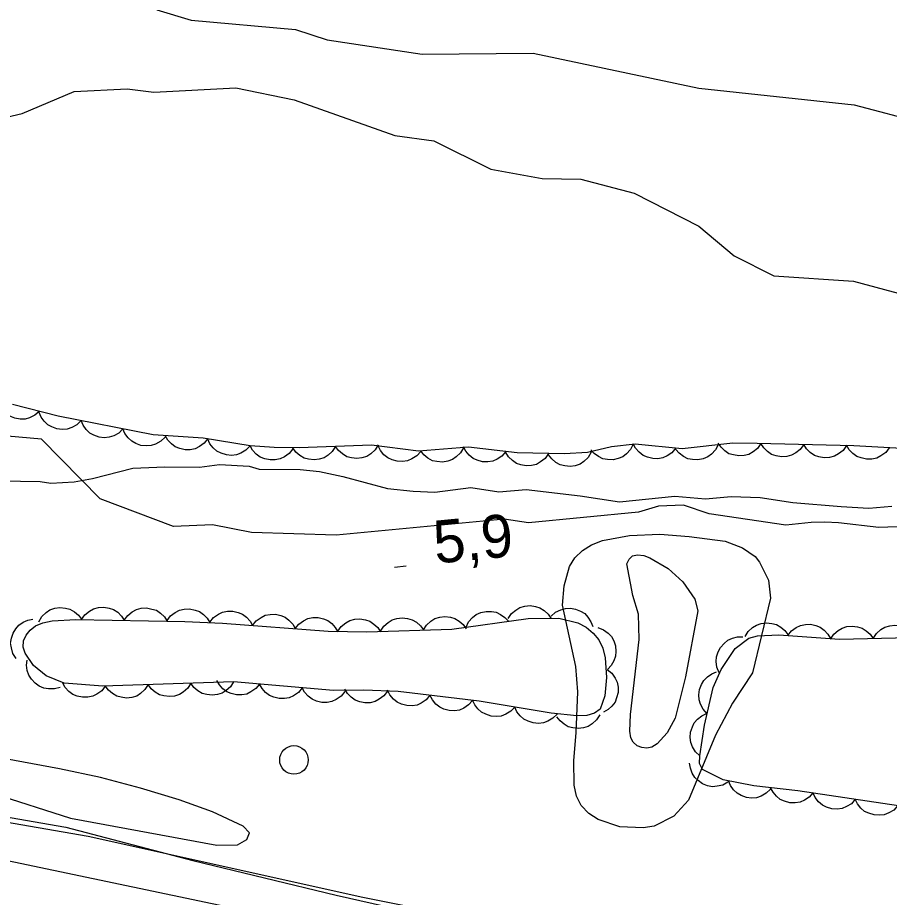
# Model space of a CAD drawing. Extents: x 336540 to 340074, y 5572036 to 5573747.
# Drawn here: x 336721.6 to 336782.8, y 5572625.9 to 5572687.6 of the extents above; entities that cross this region are included whole.
import ezdxf

# ---------------------------------------------------------------- set-up
doc = ezdxf.new("R2010")
doc.units = 0
for name, color, linetype in [('Niveau 1', 7, 'Continuous'), ('Niveau 2', 7, 'Continuous'), ('Niveau 21', 7, 'Continuous'), ('Niveau 22', 7, 'Continuous'), ('Niveau 3', 7, 'Continuous'), ('Niveau 36', 7, 'Continuous'), ('Niveau 44', 7, 'Continuous')]:
    doc.layers.add(name, color=color, linetype=linetype)

msp = doc.modelspace()

# ---------------------------------------------------------------- linework, layer by layer
at = {"layer": 'Niveau 1'}
for points in [[(336719.12, 5572680.18), (336721.97, 5572680.83), (336725.6, 5572682.39), (336729.32, 5572682.58), (336731.2, 5572682.33), (336736.94, 5572682.63), (336741.03, 5572681.81), (336748.1, 5572679.3), (336750.82, 5572678.93), (336754.82, 5572676.93), (336758.42, 5572676.29), (336761.13, 5572676.24), (336764.89, 5572675.25), (336769.42, 5572672.94), (336771.89, 5572670.86), (336774.67, 5572669.47), (336780.27, 5572669.08), (336787.14, 5572667.24)], [(336755.77, 5572652.39), (336743.97, 5572651.27), (336738.05, 5572651.47), (336735.31, 5572652.01), (336732.58, 5572651.88), (336727.42, 5572653.82), (336723.31, 5572658.01), (336720.93, 5572658.23)], [(336785.87, 5572651.96), (336782.04, 5572651.81), (336779.22, 5572652.14), (336778.26, 5572652.18), (336777.3, 5572652.16), (336775.51, 5572651.97), (336770.15, 5572652.78), (336768.34, 5572653.39), (336766.59, 5572653.31), (336765.18, 5572652.89), (336757.46, 5572652.15), (336755.77, 5572652.39)], [(336719.92, 5572633.16), (336725.34, 5572631.43), (336735.61, 5572629.55), (336737.06, 5572629.56), (336737.71, 5572629.95), (336737.9, 5572630.42), (336737.45, 5572630.87), (336735.3, 5572631.88), (336732.96, 5572632.72), (336730.25, 5572633.55), (336727.46, 5572634.28), (336724.57, 5572634.9), (336718.25, 5572636.06)]]:
    msp.add_lwpolyline(points, dxfattribs=at)
at = {"layer": 'Niveau 2'}
for points in [[(336731.4, 5572688.1), (336733.81, 5572687.39), (336741.12, 5572686.74), (336743.36, 5572686.01), (336750.01, 5572684.99), (336757.79, 5572685.08), (336769.42, 5572682.62), (336780.31, 5572681.46), (336785.11, 5572680.18)], [(336773.18, 5572641.63), (336771.78, 5572639.49), (336770.59, 5572637.26), (336768.7, 5572632.69), (336767.67, 5572631.57), (336766.28, 5572630.88), (336765.51, 5572630.75), (336763.88, 5572630.83), (336762.35, 5572631.34), (336761.69, 5572631.77), (336761.17, 5572632.33), (336760.84, 5572632.98), (336760.68, 5572633.75), (336760.64, 5572635.49), (336760.81, 5572637.41), (336760.93, 5572640.29), (336760.79, 5572642.06), (336759.85, 5572646.36), (336759.98, 5572647.73), (336760.35, 5572649.09), (336760.72, 5572649.7), (336761.25, 5572650.21), (336761.88, 5572650.61), (336762.66, 5572650.91), (336764.55, 5572651.26), (336766.67, 5572651.36), (336768.74, 5572651.19), (336771.26, 5572650.85), (336772.47, 5572650.4), (336773.36, 5572649.79), (336773.67, 5572649.39), (336774.29, 5572648.13), (336774.44, 5572646.87), (336773.18, 5572641.63)], [(336768.49, 5572641.34), (336767.76, 5572638.46), (336767.19, 5572637.41), (336766.5, 5572636.64), (336766.12, 5572636.42), (336765.76, 5572636.34), (336765.41, 5572636.39), (336765.09, 5572636.51), (336764.81, 5572636.76), (336764.65, 5572637.08), (336764.58, 5572637.54), (336764.62, 5572638.7), (336765.24, 5572643.96), (336765.19, 5572645.74), (336764.78, 5572647.04), (336764.37, 5572649.28), (336764.52, 5572649.6), (336764.76, 5572649.82), (336765.12, 5572649.89), (336765.55, 5572649.85), (336765.98, 5572649.7), (336767.27, 5572648.94), (336768.29, 5572648), (336769.14, 5572646.78), (336769.35, 5572645.97), (336768.49, 5572641.34)], [(336713.42, 5572632.82), (336725.03, 5572630.81), (336733.92, 5572628.47), (336743.97, 5572626.03), (336752.69, 5572624.08), (336763.24, 5572622.14), (336768.44, 5572621.3), (336771.02, 5572620.78), (336778.47, 5572618.92), (336781.06, 5572618.37), (336793.28, 5572616.04), (336801.03, 5572614.89), (336807.06, 5572613.73), (336818.29, 5572611.16), (336824.41, 5572609.93), (336829.29, 5572608.65), (336842, 5572605.62), (336849.91, 5572604.12), (336857.65, 5572602.37), (336860.36, 5572601.83), (336879.35, 5572598.2)]]:
    msp.add_lwpolyline(points, dxfattribs=at)
at = {"layer": 'Niveau 21'}
for points in [[(336606.59, 5572651.01), (336621.47, 5572648.81), (336627.74, 5572648.08), (336639.17, 5572646.47), (336647.1, 5572645.49), (336657.38, 5572643.66), (336675.17, 5572640.65), (336682.41, 5572638.89), (336706.84, 5572634.15), (336717.79, 5572631.7), (336726.58, 5572630.17), (336745.85, 5572625.9), (336758.27, 5572623.43), (336771.07, 5572620.58), (336780.38, 5572618.79), (336792.82, 5572616.01), (336801.98, 5572614.39), (336808.26, 5572613.12), (336817.36, 5572611.07), (336821.93, 5572609.72), (336824.69, 5572609.01), (336834.02, 5572607.19), (336854.11, 5572603.04), (336864.11, 5572601.24)], [(336884.31, 5572594.33), (336807.63, 5572610.39), (336785.16, 5572615.03), (336774.53, 5572617.32), (336763.55, 5572619.49), (336721.38, 5572628.36), (336711.63, 5572630.35), (336697.48, 5572632.86), (336693.75, 5572633.89), (336687.67, 5572635.19), (336673.64, 5572637.31), (336661.28, 5572639.55), (336653.39, 5572640.86), (336644.64, 5572642.06), (336630.46, 5572644.24), (336616.57, 5572646.25), (336606.76, 5572647.5)]]:
    msp.add_lwpolyline(points, dxfattribs=at)
at = {"layer": 'Niveau 22'}
msp.add_lwpolyline([(336720.47, 5572655.09), (336723.23, 5572655.03), (336723.97, 5572654.93), (336725.6, 5572655.02), (336726.9, 5572655.26), (336729.71, 5572655.98), (336731.97, 5572656.06), (336734.4, 5572656.04), (336735.8, 5572656.24), (336737.89, 5572656.12), (336738.58, 5572655.91), (336741.45, 5572655.88), (336742.8, 5572655.74), (336744.45, 5572655.38), (336747.57, 5572654.54), (336749.38, 5572654.36), (336750.9, 5572654.3), (336753.42, 5572654.61), (336755.39, 5572654.32), (336757.31, 5572654.49), (336761.1, 5572654.04), (336763.84, 5572653.61), (336767.73, 5572654.01), (336769.88, 5572653.83), (336771.68, 5572653.98), (336773.72, 5572653.91), (336776.01, 5572653.56), (336779.4, 5572653.3), (336781.33, 5572653.17), (336782.96, 5572653.32)], dxfattribs=at)
at = {"layer": 'Niveau 3'}
msp.add_line((336748.08, 5572649.04), (336748.88, 5572649.12), dxfattribs=at)
at = {"layer": 'Niveau 36'}
msp.add_circle((336741.019, 5572635.521), 1, dxfattribs=at)
at = {"layer": 'Niveau 44'}
for points in [[(336723.16, 5572659.96), (336722.85, 5572659.68), (336722.48, 5572659.51), (336722.16, 5572659.42), (336721.81, 5572659.41), (336721.45, 5572659.47), (336721.1, 5572659.63), (336720.81, 5572659.79), (336720.58, 5572660.05), (336720.37, 5572660.36), (336720.25, 5572660.7)], [(336783.65, 5572657.36), (336780.29, 5572657.55), (336773.51, 5572657.71), (336771.79, 5572657.73), (336768.25, 5572657.34), (336764.95, 5572657.67), (336763.3, 5572657.46), (336761.6, 5572657.07), (336759.99, 5572656.97), (336756.68, 5572657.05), (336753.26, 5572657.44), (336749.75, 5572657.17), (336746.46, 5572657.59), (336741.39, 5572657.41), (336739.63, 5572657.43), (336737.95, 5572657.54), (336734.66, 5572658.07), (336731.14, 5572658.32), (336724.48, 5572659.63), (336721.27, 5572660.44)], [(336726.09, 5572659.31), (336725.79, 5572659.02), (336725.43, 5572658.83), (336725.12, 5572658.71), (336724.77, 5572658.69), (336724.4, 5572658.73), (336724.05, 5572658.87), (336723.75, 5572659.01), (336723.5, 5572659.26), (336723.29, 5572659.56), (336723.14, 5572659.89)], [(336729.03, 5572658.73), (336728.74, 5572658.44), (336728.38, 5572658.25), (336728.07, 5572658.14), (336727.72, 5572658.11), (336727.35, 5572658.15), (336726.99, 5572658.29), (336726.7, 5572658.44), (336726.45, 5572658.68), (336726.23, 5572658.98), (336726.09, 5572659.31)], [(336731.98, 5572658.16), (336731.68, 5572657.86), (336731.32, 5572657.67), (336731.01, 5572657.56), (336730.66, 5572657.53), (336730.29, 5572657.57), (336729.93, 5572657.71), (336729.64, 5572657.86), (336729.39, 5572658.1), (336729.17, 5572658.4), (336729.03, 5572658.73)], [(336734.98, 5572658.05), (336734.72, 5572657.72), (336734.39, 5572657.49), (336734.1, 5572657.33), (336733.75, 5572657.27), (336733.38, 5572657.26), (336733.01, 5572657.35), (336732.7, 5572657.46), (336732.42, 5572657.68), (336732.17, 5572657.95), (336731.99, 5572658.26)], [(336737.94, 5572657.54), (336737.65, 5572657.24), (336737.3, 5572657.03), (336737, 5572656.91), (336736.65, 5572656.87), (336736.28, 5572656.9), (336735.91, 5572657.03), (336735.62, 5572657.16), (336735.36, 5572657.4), (336735.13, 5572657.69), (336734.98, 5572658.02)], [(336764.81, 5572657.65), (336764.63, 5572657.28), (336764.34, 5572656.99), (336764.09, 5572656.78), (336763.76, 5572656.65), (336763.4, 5572656.57), (336763.02, 5572656.59), (336762.69, 5572656.63), (336762.38, 5572656.79), (336762.08, 5572657), (336761.84, 5572657.27)], [(336767.8, 5572657.39), (336767.53, 5572657.06), (336767.19, 5572656.84), (336766.89, 5572656.7), (336766.55, 5572656.64), (336766.18, 5572656.65), (336765.81, 5572656.75), (336765.5, 5572656.87), (336765.23, 5572657.09), (336764.98, 5572657.37), (336764.81, 5572657.68)], [(336773.77, 5572657.71), (336773.54, 5572657.36), (336773.22, 5572657.11), (336772.93, 5572656.94), (336772.59, 5572656.86), (336772.22, 5572656.83), (336771.85, 5572656.9), (336771.53, 5572656.99), (336771.24, 5572657.19), (336770.97, 5572657.44), (336770.78, 5572657.74)], [(336776.77, 5572657.63), (336776.53, 5572657.29), (336776.21, 5572657.04), (336775.92, 5572656.88), (336775.58, 5572656.8), (336775.21, 5572656.77), (336774.84, 5572656.85), (336774.52, 5572656.94), (336774.24, 5572657.14), (336773.97, 5572657.4), (336773.77, 5572657.7)], [(336740.93, 5572657.34), (336740.68, 5572657.01), (336740.35, 5572656.78), (336740.05, 5572656.63), (336739.71, 5572656.56), (336739.34, 5572656.55), (336738.97, 5572656.64), (336738.66, 5572656.75), (336738.38, 5572656.96), (336738.12, 5572657.23), (336737.94, 5572657.54)], [(336743.94, 5572657.5), (336743.71, 5572657.15), (336743.41, 5572656.88), (336743.13, 5572656.7), (336742.79, 5572656.6), (336742.43, 5572656.55), (336742.05, 5572656.6), (336741.73, 5572656.68), (336741.43, 5572656.86), (336741.15, 5572657.1), (336740.94, 5572657.39)], [(336746.93, 5572657.61), (336746.71, 5572657.25), (336746.41, 5572656.99), (336746.13, 5572656.8), (336745.79, 5572656.7), (336745.43, 5572656.66), (336745.05, 5572656.71), (336744.73, 5572656.78), (336744.43, 5572656.97), (336744.15, 5572657.21), (336743.94, 5572657.5)], [(336749.91, 5572657.15), (336749.63, 5572656.84), (336749.28, 5572656.62), (336748.98, 5572656.49), (336748.63, 5572656.44), (336748.26, 5572656.46), (336747.9, 5572656.57), (336747.6, 5572656.69), (336747.33, 5572656.92), (336747.09, 5572657.21), (336746.93, 5572657.53)], [(336752.9, 5572657.41), (336752.69, 5572657.05), (336752.4, 5572656.77), (336752.13, 5572656.58), (336751.8, 5572656.46), (336751.43, 5572656.4), (336751.05, 5572656.44), (336750.73, 5572656.5), (336750.42, 5572656.67), (336750.13, 5572656.9), (336749.91, 5572657.18)], [(336755.88, 5572657.14), (336755.61, 5572656.82), (336755.26, 5572656.61), (336754.97, 5572656.47), (336754.62, 5572656.42), (336754.25, 5572656.43), (336753.88, 5572656.53), (336753.58, 5572656.65), (336753.31, 5572656.88), (336753.07, 5572657.16), (336752.9, 5572657.48)], [(336758.87, 5572657), (336758.63, 5572656.66), (336758.31, 5572656.41), (336758.02, 5572656.24), (336757.68, 5572656.16), (336757.31, 5572656.14), (336756.94, 5572656.21), (336756.62, 5572656.31), (336756.34, 5572656.51), (336756.07, 5572656.77), (336755.87, 5572657.07)], [(336761.87, 5572657.09), (336761.66, 5572656.73), (336761.36, 5572656.45), (336761.09, 5572656.26), (336760.75, 5572656.15), (336760.39, 5572656.1), (336760.01, 5572656.14), (336759.69, 5572656.21), (336759.38, 5572656.38), (336759.1, 5572656.62), (336758.88, 5572656.9)], [(336770.78, 5572657.62), (336770.59, 5572657.25), (336770.3, 5572656.96), (336770.04, 5572656.76), (336769.71, 5572656.63), (336769.35, 5572656.56), (336768.97, 5572656.58), (336768.64, 5572656.63), (336768.33, 5572656.8), (336768.03, 5572657.02), (336767.8, 5572657.29)], [(336779.77, 5572657.56), (336779.53, 5572657.22), (336779.21, 5572656.97), (336778.92, 5572656.81), (336778.58, 5572656.73), (336778.21, 5572656.7), (336777.84, 5572656.78), (336777.52, 5572656.87), (336777.23, 5572657.07), (336776.97, 5572657.33), (336776.77, 5572657.63)], [(336782.77, 5572657.41), (336782.52, 5572657.08), (336782.19, 5572656.84), (336781.89, 5572656.68), (336781.55, 5572656.61), (336781.18, 5572656.6), (336780.81, 5572656.69), (336780.5, 5572656.79), (336780.22, 5572657), (336779.96, 5572657.27), (336779.77, 5572657.58)], [(336723.13, 5572645.21), (336723.34, 5572645.57), (336723.64, 5572645.85), (336723.91, 5572646.04), (336724.25, 5572646.15), (336724.61, 5572646.2), (336724.99, 5572646.16), (336725.31, 5572646.09), (336725.62, 5572645.91), (336725.9, 5572645.68), (336726.12, 5572645.39)], [(336726.12, 5572645.36), (336726.36, 5572645.7), (336726.69, 5572645.95), (336726.97, 5572646.12), (336727.31, 5572646.21), (336727.68, 5572646.23), (336728.06, 5572646.16), (336728.37, 5572646.07), (336728.66, 5572645.87), (336728.93, 5572645.61), (336729.12, 5572645.31)], [(336729.12, 5572645.31), (336729.36, 5572645.65), (336729.68, 5572645.9), (336729.97, 5572646.07), (336730.31, 5572646.15), (336730.68, 5572646.18), (336731.06, 5572646.1), (336731.37, 5572646.01), (336731.66, 5572645.81), (336731.93, 5572645.55), (336732.12, 5572645.25)], [(336732.12, 5572645.29), (336732.37, 5572645.62), (336732.7, 5572645.86), (336732.99, 5572646.02), (336733.33, 5572646.1), (336733.7, 5572646.11), (336734.08, 5572646.03), (336734.39, 5572645.93), (336734.67, 5572645.72), (336734.93, 5572645.46), (336735.12, 5572645.15)], [(336735.12, 5572645.18), (336735.38, 5572645.5), (336735.72, 5572645.74), (336736.01, 5572645.89), (336736.36, 5572645.95), (336736.73, 5572645.95), (336737.1, 5572645.86), (336737.4, 5572645.75), (336737.68, 5572645.54), (336737.94, 5572645.26), (336738.11, 5572644.95)], [(336753.09, 5572644.83), (336753.27, 5572645.2), (336753.55, 5572645.5), (336753.8, 5572645.71), (336754.13, 5572645.85), (336754.49, 5572645.93), (336754.87, 5572645.92), (336755.19, 5572645.88), (336755.51, 5572645.72), (336755.82, 5572645.51), (336756.06, 5572645.25)], [(336756.04, 5572645.43), (336756.27, 5572645.78), (336756.59, 5572646.03), (336756.87, 5572646.21), (336757.21, 5572646.3), (336757.58, 5572646.34), (336757.95, 5572646.28), (336758.27, 5572646.19), (336758.56, 5572646), (336758.84, 5572645.75), (336759.04, 5572645.45)], [(336759.06, 5572645.59), (336759.37, 5572645.87), (336759.74, 5572646.05), (336760.06, 5572646.14), (336760.41, 5572646.15), (336760.77, 5572646.09), (336761.12, 5572645.94), (336761.41, 5572645.78), (336761.64, 5572645.52), (336761.85, 5572645.21), (336761.97, 5572644.87)], [(336721.54, 5572642.63), (336721.31, 5572642.98), (336721.2, 5572643.38), (336721.15, 5572643.7), (336721.2, 5572644.05), (336721.32, 5572644.4), (336721.52, 5572644.72), (336721.73, 5572644.98), (336722.02, 5572645.17), (336722.36, 5572645.33), (336722.71, 5572645.39)], [(336736.79, 5572641), (336727.62, 5572640.7), (336724.9, 5572640.9), (336723.65, 5572641.41), (336722.75, 5572642.15), (336722.16, 5572643), (336722.03, 5572643.43), (336722.06, 5572643.86), (336722.23, 5572644.26), (336722.52, 5572644.62), (336722.9, 5572644.92), (336723.4, 5572645.14), (336724.06, 5572645.27), (336725.72, 5572645.37), (336733.37, 5572645.23), (336736.01, 5572645.11), (336743.43, 5572644.55), (336746.13, 5572644.51), (336752.1, 5572644.69), (336757.44, 5572645.44), (336759.6, 5572645.46), (336760.92, 5572645.13), (336761.51, 5572644.82), (336762.01, 5572644.41), (336762.4, 5572643.93), (336762.68, 5572643.35), (336762.84, 5572642.68), (336762.94, 5572641.29), (336762.83, 5572640.01), (336762.5, 5572639.08), (336762.1, 5572638.79), (336761.56, 5572638.64), (336760.87, 5572638.61), (336759.05, 5572638.81), (336754.01, 5572639.64), (336748.32, 5572640.31), (336745.92, 5572640.42), (336743.8, 5572640.38), (336736.79, 5572641)], [(336738.11, 5572644.95), (336738.37, 5572645.28), (336738.71, 5572645.51), (336739, 5572645.66), (336739.35, 5572645.72), (336739.72, 5572645.73), (336740.09, 5572645.64), (336740.4, 5572645.53), (336740.67, 5572645.31), (336740.93, 5572645.04), (336741.11, 5572644.73)], [(336741.11, 5572644.73), (336741.37, 5572645.05), (336741.7, 5572645.28), (336741.99, 5572645.43), (336742.34, 5572645.5), (336742.71, 5572645.5), (336743.08, 5572645.41), (336743.39, 5572645.3), (336743.67, 5572645.08), (336743.92, 5572644.81), (336744.1, 5572644.5)], [(336744.1, 5572644.54), (336744.34, 5572644.88), (336744.66, 5572645.13), (336744.94, 5572645.3), (336745.28, 5572645.39), (336745.65, 5572645.41), (336746.03, 5572645.34), (336746.34, 5572645.25), (336746.63, 5572645.05), (336746.9, 5572644.8), (336747.1, 5572644.5)], [(336747.1, 5572644.54), (336747.32, 5572644.89), (336747.63, 5572645.16), (336747.91, 5572645.34), (336748.24, 5572645.44), (336748.61, 5572645.48), (336748.99, 5572645.43), (336749.31, 5572645.35), (336749.61, 5572645.17), (336749.89, 5572644.92), (336750.1, 5572644.63)], [(336750.1, 5572644.63), (336750.32, 5572644.98), (336750.63, 5572645.25), (336750.91, 5572645.43), (336751.24, 5572645.53), (336751.61, 5572645.57), (336751.99, 5572645.52), (336752.31, 5572645.44), (336752.61, 5572645.26), (336752.89, 5572645.01), (336753.1, 5572644.72)], [(336762.33, 5572644.8), (336762.72, 5572644.65), (336763.05, 5572644.41), (336763.28, 5572644.17), (336763.45, 5572643.86), (336763.56, 5572643.51), (336763.59, 5572643.13), (336763.58, 5572642.8), (336763.46, 5572642.47), (336763.27, 5572642.15), (336763.03, 5572641.88)], [(336772.66, 5572644.17), (336772.88, 5572644.53), (336773.18, 5572644.8), (336773.46, 5572644.98), (336773.79, 5572645.09), (336774.16, 5572645.14), (336774.54, 5572645.09), (336774.86, 5572645.02), (336775.16, 5572644.84), (336775.44, 5572644.6), (336775.66, 5572644.31)], [(336775.66, 5572644.24), (336775.91, 5572644.57), (336776.25, 5572644.8), (336776.54, 5572644.95), (336776.89, 5572645.02), (336777.25, 5572645.03), (336777.63, 5572644.94), (336777.93, 5572644.83), (336778.21, 5572644.61), (336778.47, 5572644.34), (336778.65, 5572644.03)], [(336778.65, 5572643.98), (336778.88, 5572644.33), (336779.19, 5572644.59), (336779.46, 5572644.77), (336779.8, 5572644.87), (336780.17, 5572644.91), (336780.55, 5572644.85), (336780.86, 5572644.77), (336781.16, 5572644.58), (336781.44, 5572644.34), (336781.65, 5572644.04)], [(336781.65, 5572644.04), (336781.87, 5572644.39), (336782.18, 5572644.66), (336782.46, 5572644.84), (336782.8, 5572644.93), (336783.17, 5572644.97), (336783.55, 5572644.92), (336783.86, 5572644.84), (336784.16, 5572644.65), (336784.44, 5572644.4), (336784.65, 5572644.11)], [(336814.83, 5572626.32), (336809.61, 5572627.54), (336801.55, 5572629.6), (336796.1, 5572630.77), (336784.52, 5572632.15), (336776.35, 5572633.36), (336773.28, 5572633.7), (336771.13, 5572634.13), (336769.67, 5572634.85), (336769.47, 5572635.26), (336769.48, 5572635.8), (336769.82, 5572637.96), (336770.42, 5572640.61), (336770.99, 5572641.86), (336771.96, 5572643.34), (336772.91, 5572644.06), (336773.53, 5572644.21), (336775.02, 5572644.28), (336779.27, 5572643.99), (336784.18, 5572644.1)], [(336770.84, 5572641.63), (336770.68, 5572642.02), (336770.64, 5572642.42), (336770.65, 5572642.75), (336770.76, 5572643.09), (336770.94, 5572643.41), (336771.2, 5572643.69), (336771.44, 5572643.91), (336771.77, 5572644.05), (336772.13, 5572644.14), (336772.49, 5572644.14)], [(336724.62, 5572640.61), (336724.22, 5572640.5), (336723.81, 5572640.5), (336723.48, 5572640.55), (336723.16, 5572640.69), (336722.86, 5572640.9), (336722.61, 5572641.19), (336722.42, 5572641.46), (336722.32, 5572641.79), (336722.27, 5572642.16), (336722.3, 5572642.52)], [(336762.99, 5572641.86), (336763.31, 5572641.6), (336763.54, 5572641.26), (336763.69, 5572640.97), (336763.75, 5572640.62), (336763.75, 5572640.25), (336763.65, 5572639.88), (336763.54, 5572639.58), (336763.32, 5572639.3), (336763.05, 5572639.05), (336762.73, 5572638.87)], [(336770, 5572638.76), (336769.72, 5572639.07), (336769.54, 5572639.43), (336769.43, 5572639.74), (336769.42, 5572640.09), (336769.47, 5572640.46), (336769.61, 5572640.81), (336769.77, 5572641.1), (336770.02, 5572641.35), (336770.33, 5572641.56), (336770.66, 5572641.69)], [(336736.79, 5572641), (336736.57, 5572640.65), (336736.26, 5572640.38), (336735.98, 5572640.2), (336735.65, 5572640.1), (336735.28, 5572640.05), (336734.9, 5572640.11), (336734.58, 5572640.18), (336734.28, 5572640.37), (336734, 5572640.61), (336733.79, 5572640.9)], [(336738.6, 5572640.84), (336738.34, 5572640.52), (336738, 5572640.29), (336737.71, 5572640.14), (336737.36, 5572640.08), (336736.99, 5572640.08), (336736.62, 5572640.18), (336736.31, 5572640.3), (336736.04, 5572640.51), (336735.79, 5572640.79), (336735.61, 5572641.1)], [(336727.79, 5572640.69), (336727.54, 5572640.36), (336727.2, 5572640.13), (336726.91, 5572639.98), (336726.56, 5572639.91), (336726.19, 5572639.91), (336725.82, 5572640), (336725.51, 5572640.11), (336725.23, 5572640.32), (336724.98, 5572640.6), (336724.8, 5572640.91)], [(336730.79, 5572640.8), (336730.57, 5572640.45), (336730.26, 5572640.18), (336729.99, 5572640), (336729.65, 5572639.9), (336729.28, 5572639.86), (336728.9, 5572639.91), (336728.59, 5572639.99), (336728.29, 5572640.17), (336728.01, 5572640.41), (336727.79, 5572640.71)], [(336733.79, 5572640.9), (336733.57, 5572640.55), (336733.26, 5572640.28), (336732.99, 5572640.1), (336732.65, 5572640), (336732.28, 5572639.96), (336731.9, 5572640.01), (336731.59, 5572640.09), (336731.28, 5572640.27), (336731, 5572640.51), (336730.79, 5572640.8)], [(336741.59, 5572640.58), (336741.33, 5572640.25), (336740.99, 5572640.02), (336740.69, 5572639.88), (336740.35, 5572639.82), (336739.98, 5572639.82), (336739.61, 5572639.92), (336739.3, 5572640.03), (336739.03, 5572640.25), (336738.78, 5572640.53), (336738.6, 5572640.84)], [(336744.58, 5572640.31), (336744.32, 5572639.99), (336743.98, 5572639.76), (336743.68, 5572639.61), (336743.34, 5572639.55), (336742.97, 5572639.55), (336742.6, 5572639.65), (336742.29, 5572639.77), (336742.01, 5572639.99), (336741.77, 5572640.26), (336741.59, 5572640.58)], [(336747.58, 5572640.34), (336747.33, 5572640.01), (336747, 5572639.77), (336746.71, 5572639.61), (336746.37, 5572639.53), (336746, 5572639.52), (336745.63, 5572639.6), (336745.32, 5572639.7), (336745.03, 5572639.91), (336744.77, 5572640.17), (336744.58, 5572640.48)], [(336750.56, 5572640.05), (336750.29, 5572639.73), (336749.95, 5572639.51), (336749.65, 5572639.37), (336749.3, 5572639.32), (336748.93, 5572639.34), (336748.56, 5572639.44), (336748.26, 5572639.57), (336747.99, 5572639.79), (336747.75, 5572640.08), (336747.58, 5572640.4)], [(336753.54, 5572639.69), (336753.27, 5572639.38), (336752.93, 5572639.16), (336752.63, 5572639.02), (336752.28, 5572638.97), (336751.91, 5572638.99), (336751.54, 5572639.09), (336751.24, 5572639.22), (336750.97, 5572639.44), (336750.73, 5572639.73), (336750.56, 5572640.05)], [(336756.51, 5572639.23), (336756.22, 5572638.93), (336755.87, 5572638.72), (336755.56, 5572638.6), (336755.21, 5572638.57), (336754.84, 5572638.6), (336754.48, 5572638.72), (336754.18, 5572638.86), (336753.92, 5572639.1), (336753.7, 5572639.39), (336753.55, 5572639.72)], [(336759.47, 5572638.74), (336759.18, 5572638.44), (336758.83, 5572638.24), (336758.52, 5572638.11), (336758.17, 5572638.08), (336757.8, 5572638.11), (336757.44, 5572638.23), (336757.14, 5572638.37), (336756.88, 5572638.61), (336756.66, 5572638.9), (336756.51, 5572639.23)], [(336762.46, 5572638.68), (336762.24, 5572638.32), (336761.94, 5572638.05), (336761.66, 5572637.87), (336761.33, 5572637.77), (336760.96, 5572637.72), (336760.58, 5572637.76), (336760.26, 5572637.84), (336759.96, 5572638.02), (336759.68, 5572638.26), (336759.46, 5572638.55)], [(336769.48, 5572635.81), (336769.18, 5572636.09), (336768.97, 5572636.44), (336768.85, 5572636.75), (336768.81, 5572637.1), (336768.84, 5572637.47), (336768.96, 5572637.83), (336769.09, 5572638.13), (336769.33, 5572638.39), (336769.62, 5572638.62), (336769.95, 5572638.77)], [(336771.46, 5572633.97), (336771.1, 5572633.76), (336770.7, 5572633.67), (336770.37, 5572633.64), (336770.03, 5572633.71), (336769.68, 5572633.84), (336769.37, 5572634.07), (336769.13, 5572634.29), (336768.95, 5572634.59), (336768.82, 5572634.94), (336768.77, 5572635.29)], [(336774.43, 5572633.47), (336774.14, 5572633.18), (336773.78, 5572632.99), (336773.47, 5572632.87), (336773.11, 5572632.85), (336772.75, 5572632.89), (336772.39, 5572633.03), (336772.1, 5572633.18), (336771.85, 5572633.43), (336771.63, 5572633.73), (336771.49, 5572634.06)], [(336777.43, 5572633.24), (336777.16, 5572632.92), (336776.82, 5572632.7), (336776.52, 5572632.56), (336776.17, 5572632.51), (336775.8, 5572632.52), (336775.43, 5572632.62), (336775.13, 5572632.75), (336774.86, 5572632.97), (336774.62, 5572633.25), (336774.45, 5572633.57)], [(336780.39, 5572632.76), (336780.11, 5572632.45), (336779.76, 5572632.25), (336779.46, 5572632.12), (336779.11, 5572632.08), (336778.74, 5572632.1), (336778.37, 5572632.22), (336778.08, 5572632.35), (336777.81, 5572632.59), (336777.58, 5572632.88), (336777.43, 5572633.2)], [(336783.36, 5572632.32), (336783.08, 5572632.01), (336782.73, 5572631.81), (336782.42, 5572631.68), (336782.07, 5572631.64), (336781.71, 5572631.66), (336781.34, 5572631.78), (336781.04, 5572631.91), (336780.78, 5572632.15), (336780.55, 5572632.44), (336780.39, 5572632.76)]]:
    msp.add_lwpolyline(points, dxfattribs=at)

# ---------------------------------------------------------------- texts
at = {"layer": 'Niveau 3'}
msp.add_text('5,9    ', height=3, rotation=5.5424, dxfattribs=at).set_placement((336750.95, 5572649.28))

doc.saveas('drawing.dxf')
